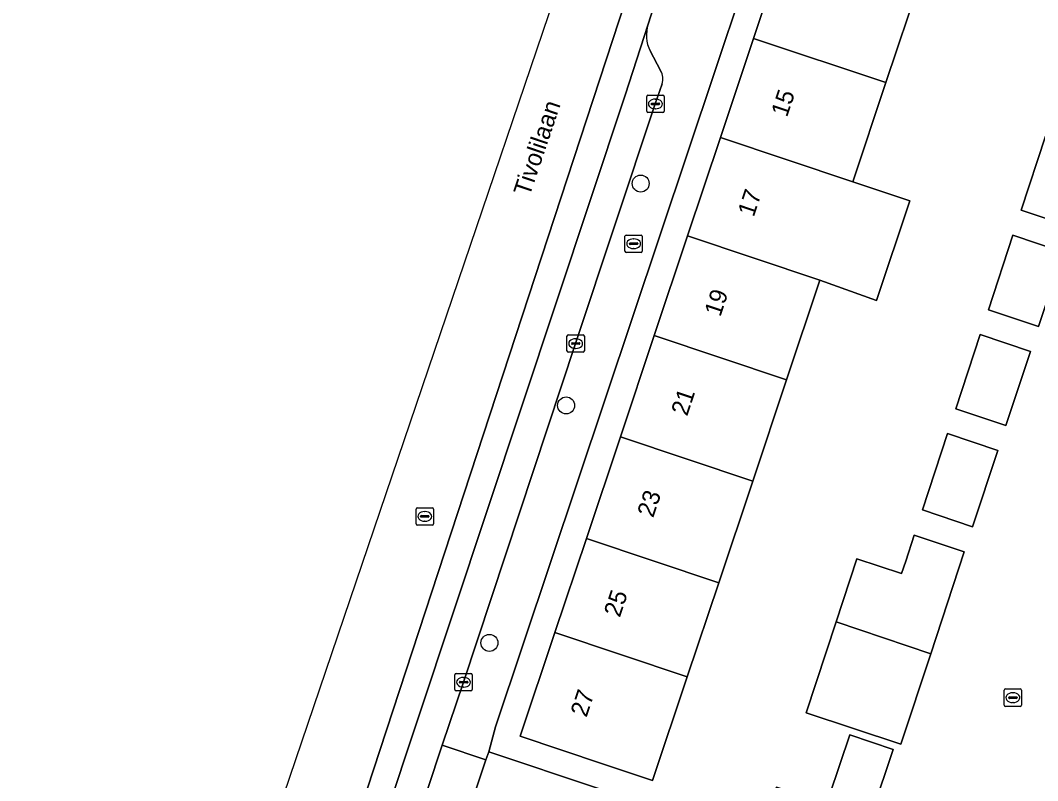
# Model space of a CAD drawing. Extents: x 163147 to 163550, y 380933 to 381639.
# Drawn here: x 163203.7 to 163262.3, y 381514.3 to 381558 of the extents above; entities that cross this region are included whole.
import ezdxf

# ---------------------------------------------------------------- set-up
doc = ezdxf.new("R2010")
doc.units = 0
for name, color, linetype in [('IMGEO_Boom', 7, 'Continuous'), ('IMGEO_Brandkraan', 7, 'Continuous'), ('IMGEO_Erf', 7, 'Continuous'), ('IMGEO_Fietspad_gesloten', 7, 'Continuous'), ('IMGEO_Kolk', 7, 'Continuous'), ('IMGEO_Openbare_ruimte_label', 7, 'Continuous'), ('IMGEO_Pand', 7, 'Continuous'), ('IMGEO_Pand_nummerreeks', 7, 'Continuous'), ('IMGEO_Parkeervlak_open', 7, 'Continuous'), ('IMGEO_Rijbaan_lokaal_gesloten', 7, 'Continuous'), ('IMGEO_Rioolput', 7, 'Continuous'), ('IMGEO_Voetpad_open', 7, 'Continuous')]:
    doc.layers.add(name, color=color, linetype=linetype)

msp = doc.modelspace()

# ---------------------------------------------------------------- linework, layer by layer
at = {"layer": 'IMGEO_Boom'}
for centre in [(163239.462, 381548.623), (163235.165, 381535.854), (163230.745, 381522.183)]:
    msp.add_circle(centre, 0.489, dxfattribs=at)
at = {"layer": 'IMGEO_Brandkraan'}
for p, q in [((163238.556, 381544.736), (163238.556, 381545.588)), ((163238.631, 381545.662), (163239.483, 381545.662)), ((163238.815, 381545.156), (163238.815, 381545.168)), ((163239.253, 381545.119), (163238.855, 381545.119)), ((163238.858, 381545.205), (163239.256, 381545.205)), ((163239.044, 381545.442), (163239.069, 381545.442)), ((163239.299, 381545.168), (163239.299, 381545.156)), ((163239.557, 381545.588), (163239.557, 381544.736)), ((163239.483, 381544.662), (163238.631, 381544.662)), ((163239.067, 381544.882), (163239.042, 381544.882))]:
    msp.add_line(p, q, dxfattribs=at)
for points in [[(163238.556, 381544.736), (163238.556, 381545.588)], [(163238.631, 381545.662), (163239.483, 381545.662)], [(163239.557, 381545.588), (163239.557, 381544.736)], [(163239.483, 381544.662), (163238.631, 381544.662)]]:
    msp.add_lwpolyline(points, dxfattribs=at)
for centre, radius, start, end in [((163238.633, 381545.586), 0.0765, 91.55205, 178.44795), ((163238.633, 381545.586), 0.0765, 91.55205, 178.44795), ((163238.855, 381545.165), 0.0403, 85.87752, 175.75265), ((163238.852, 381545.155), 0.0366, 178.93798, 274.71019), ((163239.256, 381545.162), 0.043, 264.86636, 352.45326), ((163239.26, 381545.167), 0.0386, 1.73085, 96.63898), ((163239.481, 381545.586), 0.0765, 1.55205, 88.44795), ((163239.481, 381545.586), 0.0765, 1.55205, 88.44795), ((163238.633, 381544.738), 0.0765, 181.55205, 268.44795), ((163238.633, 381544.738), 0.0765, 181.55205, 268.44795), ((163239.481, 381544.738), 0.0765, 271.55205, 358.44795), ((163239.481, 381544.738), 0.0765, 271.55205, 358.44795)]:
    msp.add_arc(centre, radius, start, end, dxfattribs=at)
for centre, major_axis, ratio, start_param, end_param in [((163239.043, 381545.162), (-0.387, 0.002), 0.722429, 4.712389, 7.853982), ((163239.068, 381545.162), (-0.39, 0.002), 0.717154, 1.570796, 4.712389)]:
    msp.add_ellipse(centre, major_axis=major_axis, ratio=ratio, start_param=start_param, end_param=end_param, dxfattribs=at)
at = {"layer": 'IMGEO_Erf'}
for points in [[(163297.645, 381600.322), (163291.519, 381603.953), (163288.586, 381605.644), (163288.771, 381605.927), (163286.053, 381608.305), (163285.797, 381607.998), (163285.439, 381608.296), (163278.684, 381600.193), (163282.792, 381596.768), (163279.804, 381592.118), (163272.09, 381594.672), (163268.035, 381596.014), (163260.111, 381598.637), (163260.077, 381598.542), (163259.878, 381598.61), (163259.425, 381597.215), (163258.011, 381597.702), (163231.091, 381517.353), (163230.707, 381515.914), (163237.033, 381513.798)], [(163255.562, 381560.327), (163253.59, 381554.433), (163251.683, 381548.732), (163254.974, 381547.634), (163253.057, 381541.902), (163249.784, 381543.054), (163247.87, 381537.332), (163245.919, 381531.5), (163243.962, 381525.649), (163242.15, 381520.232), (163240.152, 381514.261), (163237.27, 381515.226), (163232.528, 381516.812), (163234.525, 381522.783), (163236.338, 381528.2), (163238.295, 381534.051), (163240.245, 381539.882), (163242.166, 381545.624), (163244.059, 381551.281), (163245.966, 381556.982), (163247.938, 381562.876)]]:
    msp.add_lwpolyline(points, dxfattribs=at)
for points in [[(163264.275, 381546.128), (163261.389, 381547.094), (163262.793, 381551.356), (163265.68, 381550.391)], [(163262.383, 381540.388), (163259.499, 381541.361), (163260.912, 381545.647), (163263.798, 381544.681)], [(163260.508, 381534.698), (163257.621, 381535.663), (163259.029, 381539.935), (163261.913, 381538.962)], [(163258.586, 381528.869), (163255.7, 381529.835), (163257.148, 381534.229), (163260.035, 381533.264)], [(163254.459, 381516.346), (163248.995, 381518.147), (163250.722, 381523.387), (163251.923, 381527.031), (163254.496, 381526.183), (163254.73, 381526.893), (163255.223, 381528.387), (163258.109, 381527.421), (163256.178, 381521.562)], [(163246.236, 381510.75), (163247.285, 381513.875), (163250.175, 381512.905), (163250.348, 381513.422), (163251.51, 381516.885), (163254.007, 381516.046), (163251.602, 381508.881)]]:
    msp.add_lwpolyline(points, close=True, dxfattribs=at)
at = {"layer": 'IMGEO_Fietspad_gesloten'}
for points in [[(163259.597, 381612.156), (163261.884, 381614.845), (163259.826, 381616.311), (163255.545, 381608.986), (163253.519, 381605.619), (163248.986, 381592.289), (163241.568, 381568.239), (163223.711, 381513.764)], [(163205.141, 381437.39), (163214.084, 381475.132), (163214.995, 381479.021), (163218.191, 381491.718), (163219.555, 381496.475), (163219.682, 381496.916), (163220.06, 381498.046), (163220.71, 381500), (163238.567, 381553.72), (163239.892, 381557.795), (163241.214, 381561.974), (163253.553, 381600.588)]]:
    msp.add_lwpolyline(points, dxfattribs=at)
at = {"layer": 'IMGEO_Kolk'}
for p, q in [((163239.809, 381552.783), (163239.809, 381553.635)), ((163239.884, 381553.709), (163240.736, 381553.709)), ((163240.297, 381553.489), (163240.322, 381553.489)), ((163240.81, 381553.635), (163240.81, 381552.783)), ((163240.736, 381552.709), (163239.884, 381552.709)), ((163240.068, 381553.203), (163240.068, 381553.215)), ((163240.506, 381553.166), (163240.108, 381553.166)), ((163240.111, 381553.252), (163240.509, 381553.252)), ((163240.32, 381552.929), (163240.295, 381552.929)), ((163240.552, 381553.215), (163240.552, 381553.203)), ((163235.216, 381538.988), (163235.216, 381539.84)), ((163235.291, 381539.914), (163236.143, 381539.914)), ((163236.217, 381539.84), (163236.217, 381538.988)), ((163235.475, 381539.408), (163235.475, 381539.42)), ((163235.913, 381539.371), (163235.515, 381539.371)), ((163235.518, 381539.457), (163235.916, 381539.457)), ((163235.704, 381539.694), (163235.729, 381539.694)), ((163235.959, 381539.42), (163235.959, 381539.408)), ((163236.143, 381538.914), (163235.291, 381538.914)), ((163235.727, 381539.134), (163235.702, 381539.134)), ((163228.756, 381519.491), (163228.756, 381520.343)), ((163228.831, 381520.417), (163229.683, 381520.417)), ((163229.015, 381519.911), (163229.015, 381519.923)), ((163229.058, 381519.96), (163229.456, 381519.96)), ((163229.244, 381520.197), (163229.269, 381520.197)), ((163229.499, 381519.923), (163229.499, 381519.911)), ((163229.757, 381520.343), (163229.757, 381519.491)), ((163229.683, 381519.417), (163228.831, 381519.417)), ((163229.453, 381519.874), (163229.055, 381519.874)), ((163229.267, 381519.637), (163229.242, 381519.637)), ((163260.408, 381518.604), (163260.408, 381519.456)), ((163260.483, 381519.53), (163261.335, 381519.53)), ((163260.896, 381519.31), (163260.921, 381519.31)), ((163261.409, 381519.456), (163261.409, 381518.604)), ((163260.667, 381519.024), (163260.667, 381519.036)), ((163261.105, 381518.987), (163260.707, 381518.987)), ((163260.71, 381519.073), (163261.108, 381519.073)), ((163260.919, 381518.75), (163260.894, 381518.75)), ((163261.151, 381519.036), (163261.151, 381519.024)), ((163261.335, 381518.53), (163260.483, 381518.53))]:
    msp.add_line(p, q, dxfattribs=at)
for points in [[(163239.809, 381552.783), (163239.809, 381553.635)], [(163239.884, 381553.709), (163240.736, 381553.709)], [(163240.81, 381553.635), (163240.81, 381552.783)], [(163240.736, 381552.709), (163239.884, 381552.709)], [(163235.216, 381538.988), (163235.216, 381539.84)], [(163235.291, 381539.914), (163236.143, 381539.914)], [(163236.217, 381539.84), (163236.217, 381538.988)], [(163236.143, 381538.914), (163235.291, 381538.914)], [(163228.756, 381519.491), (163228.756, 381520.343)], [(163228.831, 381520.417), (163229.683, 381520.417)], [(163229.757, 381520.343), (163229.757, 381519.491)], [(163229.683, 381519.417), (163228.831, 381519.417)], [(163260.408, 381518.604), (163260.408, 381519.456)], [(163260.483, 381519.53), (163261.335, 381519.53)], [(163261.409, 381519.456), (163261.409, 381518.604)], [(163261.335, 381518.53), (163260.483, 381518.53)]]:
    msp.add_lwpolyline(points, dxfattribs=at)
for centre, radius, start, end in [((163239.886, 381553.633), 0.0765, 91.55205, 178.44795), ((163239.886, 381553.633), 0.0765, 91.55205, 178.44795), ((163240.734, 381553.633), 0.0765, 1.55205, 88.44795), ((163240.734, 381553.633), 0.0765, 1.55205, 88.44795), ((163239.886, 381552.785), 0.0765, 181.55205, 268.44795), ((163239.886, 381552.785), 0.0765, 181.55205, 268.44795), ((163240.108, 381553.212), 0.0403, 85.87752, 175.75265), ((163240.105, 381553.202), 0.0366, 178.93798, 274.71019), ((163240.509, 381553.209), 0.043, 264.86636, 352.45326), ((163240.513, 381553.214), 0.0386, 1.73085, 96.63898), ((163240.734, 381552.785), 0.0765, 271.55205, 358.44795), ((163240.734, 381552.785), 0.0765, 271.55205, 358.44795), ((163235.293, 381539.838), 0.0765, 91.55205, 178.44795), ((163235.293, 381539.838), 0.0765, 91.55205, 178.44795), ((163236.141, 381539.838), 0.0765, 1.55205, 88.44795), ((163236.141, 381539.838), 0.0765, 1.55205, 88.44795), ((163235.515, 381539.417), 0.0403, 85.87752, 175.75265), ((163235.512, 381539.407), 0.0366, 178.93798, 274.71019), ((163235.916, 381539.414), 0.043, 264.86636, 352.45326), ((163235.92, 381539.419), 0.0386, 1.73085, 96.63898), ((163235.293, 381538.99), 0.0765, 181.55205, 268.44795), ((163235.293, 381538.99), 0.0765, 181.55205, 268.44795), ((163236.141, 381538.99), 0.0765, 271.55205, 358.44795), ((163236.141, 381538.99), 0.0765, 271.55205, 358.44795), ((163228.833, 381520.341), 0.0765, 91.55205, 178.44795), ((163228.833, 381520.341), 0.0765, 91.55205, 178.44795), ((163229.055, 381519.92), 0.0403, 85.87752, 175.75265), ((163229.052, 381519.91), 0.0366, 178.93798, 274.71019), ((163229.456, 381519.917), 0.043, 264.86636, 352.45326), ((163229.46, 381519.922), 0.0386, 1.73085, 96.63898), ((163229.681, 381520.341), 0.0765, 1.55205, 88.44795), ((163229.681, 381520.341), 0.0765, 1.55205, 88.44795), ((163228.833, 381519.493), 0.0765, 181.55205, 268.44795), ((163228.833, 381519.493), 0.0765, 181.55205, 268.44795), ((163229.681, 381519.493), 0.0765, 271.55205, 358.44795), ((163229.681, 381519.493), 0.0765, 271.55205, 358.44795), ((163260.485, 381519.454), 0.0765, 91.55205, 178.44795), ((163260.485, 381519.454), 0.0765, 91.55205, 178.44795), ((163261.333, 381519.454), 0.0765, 1.55205, 88.44795), ((163261.333, 381519.454), 0.0765, 1.55205, 88.44795), ((163260.707, 381519.033), 0.0403, 85.87752, 175.75265), ((163260.704, 381519.023), 0.0366, 178.93798, 274.71019), ((163261.108, 381519.03), 0.043, 264.86636, 352.45326), ((163261.112, 381519.035), 0.0386, 1.73085, 96.63898), ((163260.485, 381518.606), 0.0765, 181.55205, 268.44795), ((163260.485, 381518.606), 0.0765, 181.55205, 268.44795), ((163261.333, 381518.606), 0.0765, 271.55205, 358.44795), ((163261.333, 381518.606), 0.0765, 271.55205, 358.44795)]:
    msp.add_arc(centre, radius, start, end, dxfattribs=at)
for centre, major_axis, ratio, start_param, end_param in [((163240.296, 381553.209), (-0.387, 0.002), 0.722429, 4.712389, 7.853982), ((163240.321, 381553.209), (-0.39, 0.002), 0.717154, 1.570796, 4.712389), ((163235.703, 381539.414), (-0.387, 0.002), 0.722429, 4.712389, 7.853982), ((163235.728, 381539.414), (-0.39, 0.002), 0.717154, 1.570796, 4.712389), ((163229.243, 381519.917), (-0.387, 0.002), 0.722429, 4.712389, 7.853982), ((163229.268, 381519.917), (-0.39, 0.002), 0.717154, 1.570796, 4.712389), ((163260.895, 381519.03), (-0.387, 0.002), 0.722429, 4.712389, 7.853982), ((163260.92, 381519.03), (-0.39, 0.002), 0.717154, 1.570796, 4.712389)]:
    msp.add_ellipse(centre, major_axis=major_axis, ratio=ratio, start_param=start_param, end_param=end_param, dxfattribs=at)
at = {"layer": 'IMGEO_Pand'}
for points in [[(163253.59, 381554.433), (163255.562, 381560.327), (163247.938, 381562.876), (163245.966, 381556.982)], [(163253.59, 381554.433), (163245.966, 381556.982), (163244.059, 381551.281), (163251.683, 381548.732)], [(163242.166, 381545.624), (163249.784, 381543.054), (163253.057, 381541.902), (163254.974, 381547.634), (163251.683, 381548.732), (163244.059, 381551.281)], [(163261.389, 381547.094), (163264.275, 381546.128), (163265.68, 381550.391), (163262.793, 381551.356)], [(163242.166, 381545.624), (163240.245, 381539.882), (163247.87, 381537.332), (163249.784, 381543.054)], [(163259.499, 381541.361), (163262.383, 381540.388), (163263.798, 381544.681), (163260.912, 381545.647)], [(163238.295, 381534.051), (163245.919, 381531.5), (163247.87, 381537.332), (163240.245, 381539.882)], [(163257.621, 381535.663), (163260.508, 381534.698), (163261.913, 381538.962), (163259.029, 381539.935)], [(163238.295, 381534.051), (163236.338, 381528.2), (163243.962, 381525.649), (163245.919, 381531.5)], [(163255.7, 381529.835), (163258.586, 381528.869), (163260.035, 381533.264), (163257.148, 381534.229)], [(163242.15, 381520.232), (163243.962, 381525.649), (163236.338, 381528.2), (163234.525, 381522.783)], [(163250.722, 381523.387), (163256.178, 381521.562), (163258.109, 381527.421), (163255.223, 381528.387), (163254.73, 381526.893), (163254.496, 381526.183), (163251.923, 381527.031)], [(163256.178, 381521.562), (163250.722, 381523.387), (163248.995, 381518.147), (163254.459, 381516.346)], [(163242.15, 381520.232), (163234.525, 381522.783), (163232.528, 381516.812), (163237.27, 381515.226), (163240.152, 381514.261)], [(163254.007, 381516.046), (163251.51, 381516.885), (163250.348, 381513.422), (163250.175, 381512.905), (163247.285, 381513.875), (163246.236, 381510.75), (163251.602, 381508.881)], [(163229.448, 381512.152), (163235.774, 381510.036), (163236.027, 381510.792), (163237.033, 381513.798), (163230.707, 381515.914), (163230.55, 381515.445)]]:
    msp.add_lwpolyline(points, close=True, dxfattribs=at)
at = {"layer": 'IMGEO_Parkeervlak_open'}
for points in [[(163239.892, 381557.795), (163238.567, 381553.72), (163220.71, 381500), (163220.06, 381498.046)], [(163240.606, 381555.126), (163240, 381556.264)], [(163220.987, 381499.078), (163222.218, 381499.676), (163222.586, 381500), (163222.704, 381500.245), (163223.093, 381501.348), (163225.534, 381508.756), (163228.034, 381516.302), (163229.252, 381519.917), (163235.712, 381539.414), (163240.304, 381553.21), (163240.693, 381554.364)]]:
    msp.add_lwpolyline(points, dxfattribs=at)
for centre, radius, start, end in [((163241.866, 381557.165), 2.072, 162.29325, 205.77692), ((163239.833, 381554.652), 0.907, 341.49219, 31.53469)]:
    msp.add_arc(centre, radius, start, end, dxfattribs=at)
at = {"layer": 'IMGEO_Rijbaan_lokaal_gesloten'}
for points in [[(163259.417, 381623.955), (163248.38, 381600.231), (163214.721, 381501.163), (163212.433, 381491.793), (163200.685, 381443.671), (163197.503, 381419.325), (163194.029, 381392.739), (163150.426, 381242.7), (163152.402, 381240.561), (163154.603, 381238.177), (163155.457, 381241.614)], [(163166.425, 381280.691), (163188.546, 381358.485), (163194.244, 381378.759), (163197.853, 381391.449), (163199.503, 381397.64), (163199.813, 381399.806), (163200.997, 381406.978), (163202.361, 381414.066), (163203.421, 381419.565), (163203.421, 381421.474), (163203.421, 381430.45), (163203.421, 381436.022), (163203.704, 381437.827), (163206.489, 381449.486), (163214.12, 381481.676), (163216.801, 381492.716), (163218.451, 381497.565), (163223.711, 381513.764), (163241.568, 381568.239), (163248.986, 381592.289), (163253.519, 381605.619), (163255.545, 381608.986), (163259.826, 381616.311)]]:
    msp.add_lwpolyline(points, dxfattribs=at)
at = {"layer": 'IMGEO_Rioolput'}
for p, q in [((163226.523, 381529.038), (163226.523, 381529.89)), ((163226.598, 381529.964), (163227.45, 381529.964)), ((163227.524, 381529.89), (163227.524, 381529.038)), ((163226.782, 381529.458), (163226.782, 381529.47)), ((163227.22, 381529.421), (163226.822, 381529.421)), ((163226.825, 381529.507), (163227.223, 381529.507)), ((163227.011, 381529.744), (163227.036, 381529.744)), ((163227.266, 381529.47), (163227.266, 381529.458)), ((163227.45, 381528.964), (163226.598, 381528.964)), ((163227.034, 381529.184), (163227.009, 381529.184))]:
    msp.add_line(p, q, dxfattribs=at)
for points in [[(163226.523, 381529.038), (163226.523, 381529.89)], [(163226.598, 381529.964), (163227.45, 381529.964)], [(163227.524, 381529.89), (163227.524, 381529.038)], [(163227.45, 381528.964), (163226.598, 381528.964)]]:
    msp.add_lwpolyline(points, dxfattribs=at)
for centre, radius, start, end in [((163226.6, 381529.888), 0.0765, 91.55205, 178.44795), ((163226.6, 381529.888), 0.0765, 91.55205, 178.44795), ((163227.448, 381529.888), 0.0765, 1.55205, 88.44795), ((163227.448, 381529.888), 0.0765, 1.55205, 88.44795), ((163226.822, 381529.467), 0.0403, 85.87752, 175.75265), ((163226.819, 381529.457), 0.0366, 178.93798, 274.71019), ((163227.223, 381529.464), 0.043, 264.86636, 352.45326), ((163227.227, 381529.469), 0.0386, 1.73085, 96.63898), ((163226.6, 381529.04), 0.0765, 181.55205, 268.44795), ((163226.6, 381529.04), 0.0765, 181.55205, 268.44795), ((163227.448, 381529.04), 0.0765, 271.55205, 358.44795), ((163227.448, 381529.04), 0.0765, 271.55205, 358.44795)]:
    msp.add_arc(centre, radius, start, end, dxfattribs=at)
for centre, major_axis, ratio, start_param, end_param in [((163227.01, 381529.464), (-0.387, 0.002), 0.722429, 4.712389, 7.853982), ((163227.035, 381529.464), (-0.39, 0.002), 0.717154, 1.570796, 4.712389)]:
    msp.add_ellipse(centre, major_axis=major_axis, ratio=ratio, start_param=start_param, end_param=end_param, dxfattribs=at)
at = {"layer": 'IMGEO_Voetpad_open'}
for points in [[(163240.693, 381554.364), (163240.304, 381553.21), (163235.712, 381539.414), (163229.252, 381519.917), (163228.034, 381516.302), (163230.55, 381515.445), (163230.707, 381515.914), (163231.091, 381517.353), (163258.011, 381597.702), (163259.425, 381597.215), (163259.878, 381598.61), (163255.285, 381600.053), (163254.305, 381596.919), (163248.415, 381578.286), (163244.263, 381565.441), (163243.851, 381564.302)], [(163241.214, 381561.974), (163239.892, 381557.795)], [(163240, 381556.264), (163240.606, 381555.126)]]:
    msp.add_lwpolyline(points, dxfattribs=at)
msp.add_lwpolyline([(163230.55, 381515.445), (163228.034, 381516.302), (163225.534, 381508.756), (163228.097, 381507.872), (163229.448, 381512.152)], close=True, dxfattribs=at)
for centre, radius, start, end in [((163241.866, 381557.165), 2.072, 162.29325, 205.77692), ((163239.833, 381554.652), 0.907, 341.49219, 31.53469)]:
    msp.add_arc(centre, radius, start, end, dxfattribs=at)

# ---------------------------------------------------------------- texts
at = {"layer": 'IMGEO_Openbare_ruimte_label'}
msp.add_text('Tivolilaan', height=1, rotation=71.32942, dxfattribs=at).set_placement((163233.055, 381547.843))
at = {"layer": 'IMGEO_Pand_nummerreeks'}
for s, p in [('15', (163247.893, 381552.404)), ('17', (163245.972, 381546.661)), ('19', (163244.051, 381540.918)), ('21', (163242.136, 381535.196)), ('23', (163240.18, 381529.346)), ('25', (163238.259, 381523.603)), ('27', (163236.338, 381517.86))]:
    msp.add_text(s, height=1, rotation=71.5035, dxfattribs=at).set_placement(p)

doc.saveas('drawing.dxf')
